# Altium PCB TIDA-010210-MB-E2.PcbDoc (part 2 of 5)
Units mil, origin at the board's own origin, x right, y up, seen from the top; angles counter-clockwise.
Board outline 11811.02 x 8661.42 mil, 4 copper layers (Top Layer, Gnd Layer, Pwr Layer, Bottom Layer), stack 94.4 mil thick; 473 components, 257 nets, 1291 pads, 289 vias.
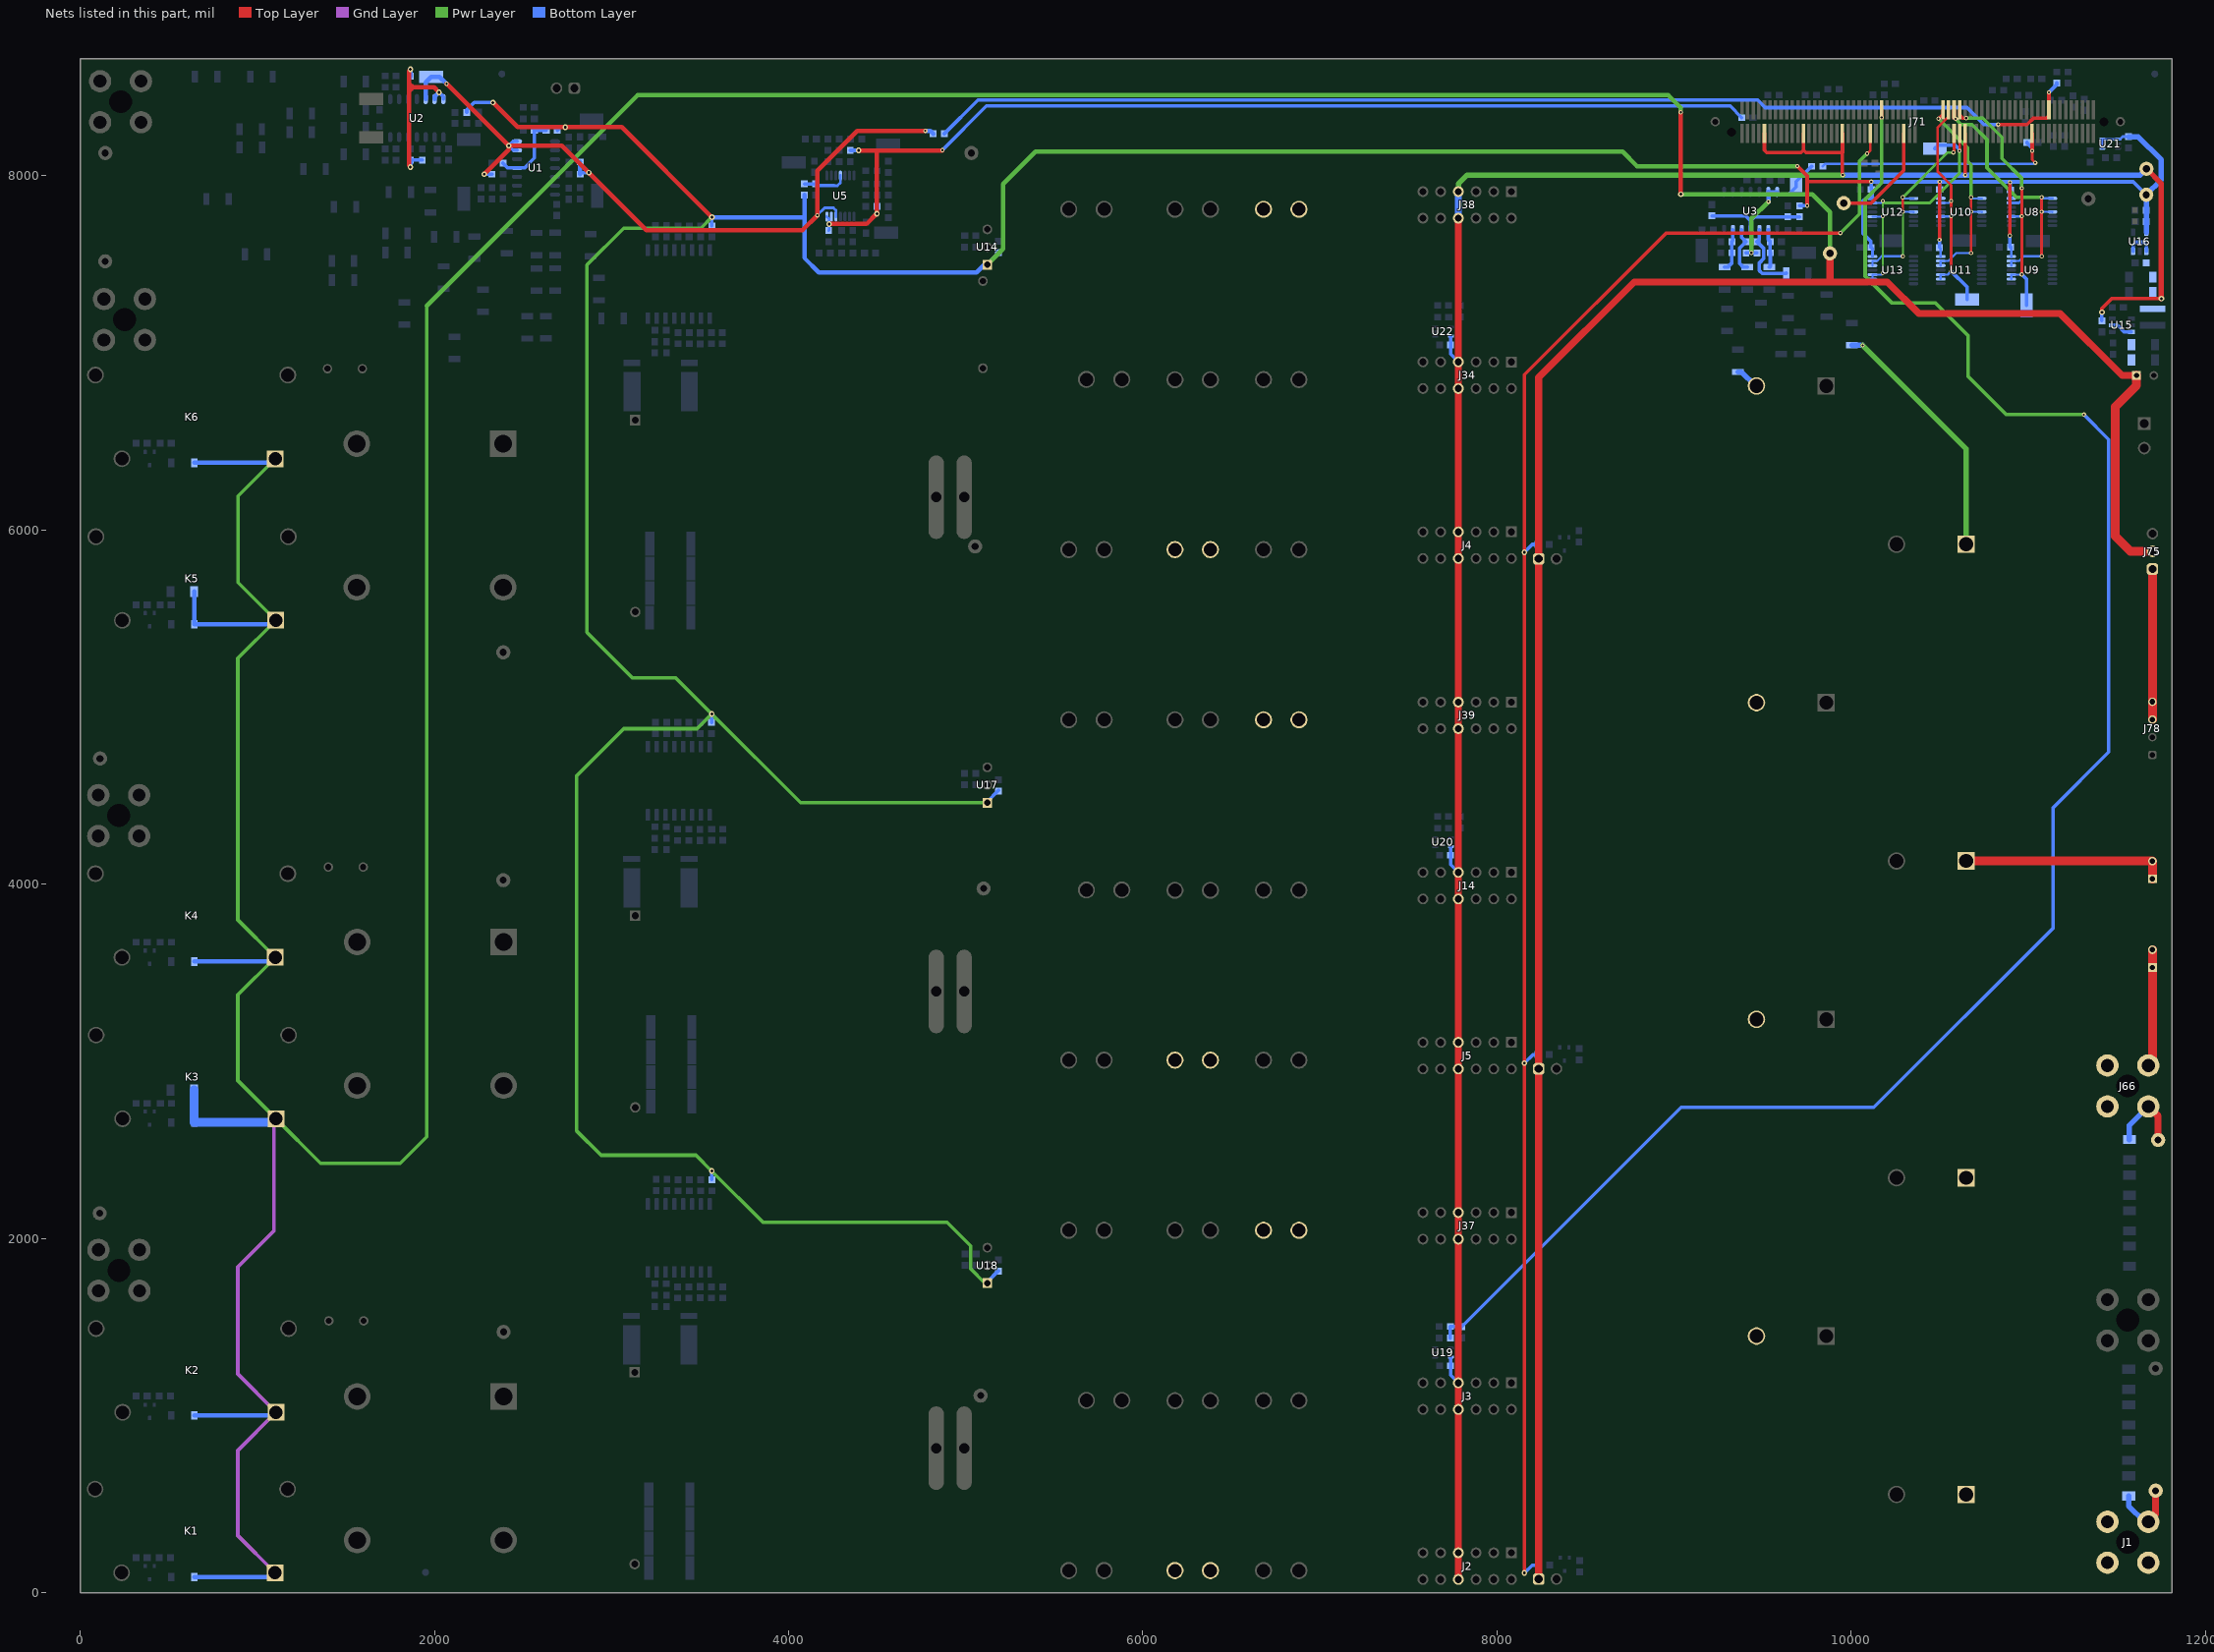
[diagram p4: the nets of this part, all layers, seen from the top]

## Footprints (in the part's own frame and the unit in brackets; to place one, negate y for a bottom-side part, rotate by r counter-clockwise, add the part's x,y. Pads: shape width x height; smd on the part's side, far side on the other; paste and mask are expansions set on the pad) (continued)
FP-7443783533220_PTH_34MM5_36MM-MFG [mm]
  rrect3% 3.8x3.8 hole 2.5 paste-1000 mask+0: 1(10.5,10.3)
  round 3.8 hole 2.5 paste-1000 mask+0: 2(-10.5,-10.3) 3(-10.5,10.3) 4(10.5,-10.3)
  silkscreen extent -18,-17.25 18.73,17.25, body extent -18.1,-17.35 18.1,17.35, height 0.25
IEC_Caution_Medium [mil]
  silkscreen extent -217,-182 217,193
IEC_HighVoltage_Medium [mil]
  silkscreen extent -217,-176 217,200
IEC_HotSurface_Medium [mil]
  silkscreen extent -217,-188 217,188
Keystone5000 [mil] "For Keystone 500x miniature loop terminals"
  round 80 hole 40: 1(0,0)
  silkscreen extent -52,-52 52,52, body extent -49,-49 49,49, height 182
Keystone5001 [mil] "For Keystone 500x miniature loop terminals"
  round 80 hole 40: 1(0,0)
  silkscreen extent -52,-52 52,52, body extent -49,-49 49,49, height 182
Keystone5002 [mil] "For Keystone 500x miniature loop terminals"
  round 80 hole 40: 1(0,0)
  silkscreen extent -52,-52 52,52, body extent -49,-49 49,49, height 182
Keystone5003 [mil] "For Keystone 500x miniature loop terminals"
  round 80 hole 40: 1(0,0)
  silkscreen extent -52,-52 52,52, body extent -49,-49 49,49, height 182
Keystone5004 [mil] "For Keystone 500x miniature loop terminals"
  round 80 hole 40: 1(0,0)
  silkscreen extent -52,-52 52,52, body extent -49,-49 49,49, height 182
Label_650x200 [mil] "Thermal Transfer Label"
  round 1 on Mech13: 0(0,0)
  silkscreen extent -325,-100 325,100, body extent -325,-100 325,100, height 1
LP0003A [mm] "TO, Flat Index; 3 In-Line, Formed Axial Leads; Body Dia. 4.8mm; Leads 0.56 x 0.41 mm (max)"
  rrect7% 1.4x1.4 hole 0.9: 1(0,2.54)
  round 1.4 hole 0.9: 2(0,0) 3(0,-2.54)
  silkscreen extent -1.35,-2.41 2.65,2.95, body extent -1.33,-2.83 2.35,2.83, height 9.01
Mill-max_310-13-102-41-001000 [mm] "Mill-Max"
  rect 1.25x1.25 hole 0.75: 1(-1.27,0)
  round 1.25 hole 0.75: 2(1.27,0)
  silkscreen extent -2.57,-1.3 2.58,1.73, body extent -2.54,-1.27 2.54,1.27, height 4.25
Mill-max_310-13-104-41-001000 [mm] "Receptacle, 2.54mm, 4x1, TH"
  rrect50% 1.2x1.2 hole 0.8 mask+0.05: 1(-3.81,0)
  round 1.2 hole 0.8 mask+0.05: 2(-1.27,0) 3(1.27,0) 4(3.81,0)
  body extent -5.08,-1.27 5.08,1.27, height 4.25
Mill-Max_0312-0-15-15-34-27-10-0 [mm] "Pin Receptacle, .032-.046\" .075\" Dia, Gold, TH"
  round 2.45 hole 1.905: 1(0,0)
  silkscreen extent -1.52,-1.52 1.52,1.52, body extent -1.15,-1.15 1.16,1.15, height 0.46
Molex_0448120024#1 [mm] "Receptacle, 2.54mm, 6x1, TH"
  round 1.55 hole 1.02: 1(-6.35,-1.905) 2(-3.81,-1.905) 2(-3.81,1.905) 3(-1.27,-1.905) 3(-1.27,1.905) 4(1.27,-1.905) 4(1.27,1.905) 5(3.81,-1.905) 5(3.81,1.905) 6(6.35,-1.905) 6(6.35,1.905)
  rect 1.55x1.55 hole 1.02: 1(-6.35,1.905)
  silkscreen extent -8.2,-4.09 8.08,3.4, body extent -7.92,-4.09 8.08,3.4, height 4.5
Molex_0448120024#2 [mm] "Receptacle, 2.54mm, 6x1, TH"
  rect 1.55x1.55 hole 1.02: 1(-6.35,-1.905)
  round 1.55 hole 1.02: 1(-6.35,1.905) 2(-3.81,-1.905) 2(-3.81,1.905) 3(-1.27,-1.905) 3(-1.27,1.905) 4(1.27,1.905) 4(1.27,-1.905) 5(3.81,-1.905) 5(3.81,1.905) 6(6.35,-1.905) 6(6.35,1.905)
  body extent -7.92,-3.4 8.08,4.09, height 4.5
Pb-Free_Overlay_Medium [mil]
  silkscreen extent -95,-95 95,95
PW0014A_N [mm] "TSOP, 14-Leads, Body 5x4.4mm, Pitch 0.65mm, IPC Medium Density"
  oval 1.4x0.45 smd: 1(-2.95,1.95) 2(-2.95,1.3) 3(-2.95,0.65) 4(-2.95,0) 5(-2.95,-0.65) 6(-2.95,-1.3) 7(-2.95,-1.95) 8(2.95,-1.95) 9(2.95,-1.3) 10(2.95,-0.65) 11(2.95,0) 12(2.95,0.65) 13(2.95,1.3) 14(2.95,1.95)
  silkscreen extent -3.4,-2.55 1.85,2.55, body extent -3.21,-2.5 3.21,2.5, height 1
RELAY_G4A-1A-PE [mm] "THD, 4-Leads, Body 30.5x16mm, Height 26.8mm"
  rect 2.4x2.4 hole 1.9: 1(-12,5.75)
  round 2.4 hole 1.9: 2(10,5.75) 3(13.8,-6.25) 4(-13.8,-6.25)
  silkscreen extent -16,-8 15.25,8, body extent -15.25,-8 15.25,8, height 26.8
SOD-123 [mm] "On Semi recommended land pattern"
  rect 0.915x1.22 smd: 1(-1.638,0) 2(1.637,0)
  silkscreen extent -2.74,-1.17 2.03,1.17, body extent -1.93,-0.9 1.93,0.9, height 1.35
SOT-323 [mm] "Diodes Inc recommended land pattern.  2016-02-24"
  rrect21% 0.6x0.47 smd: 1(-0.95,0.65) 2(-0.95,-0.65) 3(0.95,0)
  silkscreen extent -1.14,-1.22 0.77,1.22, body extent -1.13,-1.13 1.12,1.12, height 1.13
TDK_B751 [mm] "TH, 2-Leads, Dia 12.5mm, Pin Spacing 5mm"
  round 1.35 hole 0.85: 1(0,2.5) 2(0,-2.5)
  silkscreen extent -3.5,-6.25 3.5,6.25, body extent -3.48,-6.2 3.48,6.25, height 16.49
Testpoint_Keystone_Miniature [mil] "Miniature SMT test point"
  rect 135x70 smd: 1(0,0)
  silkscreen extent -78,-46 78,45, body extent -53,-20 53,20, height 61
TNPV1206 [mm] "VISHAY"
  rrect11% 0.9x1.7 smd: 1(-1.6,0) 2(1.6,0)
  silkscreen extent -2.4,-1.2 2.4,1.2, body extent -1.67,-0.87 1.67,0.87, height 0.65
VY1_1200x500_V [mm] "TH, 2-Leads, Body 12x5mm, Pin Spacing 12.5mm"
  round 1.4 hole 0.9: 1(-6.25,0) 2(6.25,0)
  silkscreen extent -3.5,-2.5 3.5,2.5, body extent -6.65,-2.5 6.65,2.5, height 15.99
WEEE_Minimum [mil] "WEEElie bin"
  silkscreen extent -95,-172 99,104
WL-SMCD-0603 [mm] "SMD, 2-Leads, Body 1.6x0.8mm"
  rrect13% 0.8x0.75 smd: 1(-0.8,0) 2(0.8,0)
  body extent -0.8,-0.4 0.8,0.4, height 0.4
WSL4026_310 [mm] "SMD, 4-Leads, Body 6.6x10.14mm"
  rect 2.44x5.6 smd: 1(-4.115,-0.9) 2(4.115,-0.9)
  rect 2.44x0.89 smd: 3(-4.115,3.235) 4(4.135,3.235)
  silkscreen extent -5.25,-3.5 5.1,3.5, body extent -5.15,-3.25 5.15,3.65, height 3.1
WURTH_61300211121 [mm] "Header, 2.54mm, 2x1, TH"
  rrect50% 1.65x1.65 hole 1.15: 1(-1.27,0)
  round 1.65 hole 1.15: 2(1.27,0)
  body extent -2.54,-1.27 2.54,1.27, height 8.54
WURTH_61300311121 [mm] "Header, 2.54mm, 3x1, TH"
  rrect50% 1.65x1.65 hole 1.15: 1(-2.54,0)
  round 1.65 hole 1.15: 2(0,0) 3(2.54,0)
  body extent -3.81,-1.27 3.81,1.27, height 8.54
Wurth_691214110002 [mm] "Receptacle, 3.5mm, 2x1, TH"
  rect 1.8x1.8 hole 1.3: 1(-1.75,0)
  round 1.8 hole 1.3: 2(1.75,0)
  silkscreen extent -3.8,-3.4 3.5,4, body extent -3.9,-3.4 3.5,4, height 8.5
Wurth_WP-THRBU [mm] "Power Element Bush, M3, TH"
  round 3.2 hole 1.85: 1(-2.935,-2.935) 1(-2.935,2.935) 1(2.935,-2.935) 1(2.935,2.935)
  round 3.1 on Top Paste: ""(-2.935,-2.935) ""(-2.935,2.935) ""(2.935,-2.935) ""(2.935,2.935)
  round 3 hole 3.3 unplated mask+0.102: ""(0,0)
  silkscreen extent -3.5,-3.5 3.5,3.5, body extent -3.5,-3.5 3.5,3.5, height 3
XAL4030 [mil] "Coilcraft XAL4030 7/18/12"
  rect 38x146 smd: 1(-46.5,0) 2(46.5,0)
  silkscreen extent -84,-84 84,84, body extent -84,-84 84,84, height 122

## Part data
C1 C2 C3 C4 C5 C6 C7 C8: library part LGN2X121MELB45, "CAP, AL, 150 uF, 550 V, +/- 20%, TH", Cap_Case=22x45mm, Manufacturer=Kemet, Tolerance_%=20, Value2=550V, ValueDisplayed=150µF
C9 C10 C11: library part CMP-0012442-3, "CAP, Film, 4.7 uF, 630 V, +/- 10%, 0.015 ohm, TH", Manufacturer=TDK, Tolerance_%=10%, Value1="0.015 ohm", Value2=630V, ValueDisplayed=4.7uF
C12 C87 C88 C105: library part CMP-0008772-2, "CAP, CERM, 10 uF, 35 V, +/- 10%, X7R, AEC-Q200 Grade 1, 1206_190", Cap_Case=1206_190, Manufacturer=TDK, Supplier Part Number 1=445-174428-1-ND, TempCo=X7R, Tolerance_%=10%, Value1="0.002229 ohm", Value2=35V, ValueDisplayed=10uF
C13: library part CMP-0064961-1, "CAP, CERM, 2200 pF, X1 760 VAC/Y1 500 VAC, +/- 10%, Y5U, D12xT5mm", Cap_Case=12x5mm, Manufacturer=Vishay-Bccomponents, TempCo=Y5U, Tolerance_%=10%, Value1=Unknown, Value2=V, ValueDisplayed=2200pF
C14 C15 C16 C20 C21 C22 C26 C27: library part CMP-0006790-4, "CAP, CERM, 470 pF, 50 V, +/- 5%, C0G/NP0, 0603", Cap_Case=0603, Manufacturer=AVX, Supplier Part Number 1=478-1183-1-ND, TempCo=C0G/NP0, Tolerance_%=5%, Value1="0.063 ohm", Value2=50V, ValueDisplayed=470pF
C17 C18 C19 C23 C24 C25 C28 C29 C31 C36 C50 C63 C74: "CAP, CERM, 0.01uF, 50V, +/-10%, X7R, 0603", Cap_Case=0603, Manufacturer=Kemet, Supplier Part Number 1=399-5346-1-ND, TempCo=X7R, Tolerance_%=10, Value1=Unknown, Value2=50V, ValueDisplayed=0.01µF
C30 C32 C33 C34 C37 C41 C45 C46 C54 C58 C59 C67 C71 C72 C73 C77 C78 C79 C80 C81 C82 C83 C84 C85 C93 C94 C96 C97 C98 C100 C101 C102 C104: library part CMP-0006979-5, "CAP, CERM, 0.1 uF, 25 V, +/- 10%, X7R, 0603", Cap_Case=0603, Manufacturer=Kemet, Supplier Part Number 1=399-5345-1-ND, TempCo=X7R, Tolerance_%=10%, Value1=Unknown, Value2=25V, ValueDisplayed=0.1uF
C35 C49 C62: library part CMP-0007210-4, "CAP, CERM, 3300 pF, 50 V, +/- 5%, C0G/NP0, 0603", Cap_Case=0603, Manufacturer=MuRata, Supplier Part Number 1=GRM1885C1H332JA01D-ND, TempCo=C0G/NP0, Tolerance_%=5%, Value1=Unknown, Value2=50V, ValueDisplayed=3300pF
C38 C51 C64: library part CMP-0007197-4, "CAP, CERM, 220 pF, 50 V, +/- 5%, C0G/NP0, 0603", Cap_Case=0603, Manufacturer=MuRata, Supplier Part Number 1=490-1435-1-ND, TempCo=C0G/NP0, Tolerance_%=5%, Value1=Unknown, Value2=50V, ValueDisplayed=220pF
C39 C42 C52 C55 C65 C68 C95 C99 C103: library part CMP-0006784-4, "CAP, CERM, 330 pF, 50 V, +/- 5%, C0G/NP0, 0603", Cap_Case=0603, Manufacturer=AVX, Supplier Part Number 1=478-1181-1-ND, TempCo=C0G/NP0, Tolerance_%=5%, Value1="0.071 ohm", Value2=50V, ValueDisplayed=330pF
C40 C44 C53 C57 C66 C70: library part CMP-0079720-1, "CAP, CERM, 1 µF, 25 V,+/- 10%, X7R, 0603", Cap_Case=0603, Manufacturer=MuRata, Supplier Part Number 1=490-10888-1-ND, TempCo=X7R, Tolerance_%=10%, Value2=25V, ValueDisplayed=1µF
C43 C47 C48 C56 C60 C61 C69 C75 C76: library part CMP-0007431-4, "CAP, CERM, 1000 pF, 50 V, +/- 5%, X7R, 0603", Cap_Case=0603, Manufacturer=MuRata, Supplier Part Number 1=490-9733-1-ND, TempCo=X7R, Tolerance_%=5%, Value1=Unknown, Value2=50V, ValueDisplayed=1000pF
C86: library part CMP-0010333-1, "CAP, AL, 100 uF, 25 V, +/- 20%, TH", Cap_Case="Radial 6.3x11.2", Manufacturer=Panasonic, Supplier Part Number 1=P13476-ND, Tolerance_%=20%, Value1=Unknown, Value2=25V, ValueDisplayed=100uF
C89 C90: library part CMP-0008959-2, "CAP, CERM, 22 uF, 10 V, +/- 10%, X7R, 1206", Cap_Case=1206, Manufacturer=MuRata, Supplier Part Number 1=490-5309-1-ND, TempCo=X7R, Tolerance_%=10%, Value1=Unknown, Value2=10V, ValueDisplayed=22uF
C91 C92: library part CMP-0079605-1, "CAP, CERM, 2.2 µF, 16 V,+/- 10%, X7R, 0603", Cap_Case=0603, Manufacturer="Yageo America", Supplier Part Number 1=311-3490-1-ND, TempCo=X7R, Tolerance_%=10%, Value2=16V, ValueDisplayed=2.2µF
D1 D2 D3 D4 D5 D6: library part CMP-0750148-1, "Diode, Switching, 100 V, 0.3 A, AEC-Q101, SOD-123", Manufacturer="Diodes Inc.", Value1=0.3A, Value2=1.25V
D7 D8: library part CMP-0081648-2, "LED, Green, SMD", Color=Green, Manufacturer="Wurth Elektronik", Power_TotalModule=48mW, Value1=0.048W, Value2=2V
FID1 FID2 FID3: library part CMP-0077181-1, "Fiducial mark.  There is nothing to buy or mount.", Manufacturer=N/A
J1 J31 J66 J67 J68 J69 J70: library part CMP-0078526-1, "Power Element Bush, M3, TH", Current_A=50A, Manufacturer="Wurth Elektronik", Supplier Part Number 1=732-10882-1-ND
J2 J3 J4 J5 J14 J34 J37 J38 J39: "Receptacle, 2.54mm, 6x1, Gold, TH", Manufacturer=Molex, Supplier Part Number 1=WM18605-ND
J6 J7 J8 J9 J10 J11 J12 J13 J15 J16 J17 J18 J19 J20 J21 J22 J23 J24 J25 J26 J27 J28 J29 J30 J32 J33 J35 J36 J40 J41 J42 J43 J44 J45 J46 J47 J48 J49 J50 J51 J52 J53 J54 J55 J56 J57 J58 J59 J60 J61 J62 J63 J64 J65: library part 0312-0-15-15-34-27-10-0, "Pin Receptacle, .032-.046\" .075\" Dia, Gold, TH", Manufacturer=Mill-Max, Supplier Part Number 1=0312-015153427100-ND
J71: library part CMP-0003814-2, "C2000 controlCARD-120HSEC connector, SMT", Manufacturer=Samtec
J72 J79 J80 J81: library part CMP-0054794-2, "Header, 2.54 mm, 2x1, Gold, TH", Color=Black, Manufacturer="Wurth Elektronik", Supplier Part Number 1=732-5315-ND
J74: library part CMP-0054825-2, "Terminal Block, 3.5mm, 2x1, Tin, TH", Color=Green, Current_A=10A, Manufacturer="Wurth Elektronik", Supplier Part Number 1=732-2747-ND, Voltage_V=300V
J75: library part CMP-0054796-2, "Header, 2.54 mm, 3x1, Gold, TH", Color=Black, Manufacturer="Wurth Elektronik", Supplier Part Number 1=732-5316-ND
J76 J77: library part CMP-0055073-1, "Socket Strip, 100mil, 2x1, Gold, TH", Manufacturer=Mill-Max, Supplier Part Number 1=ED7402-ND
J78: library part CMP-0084081-1, "Receptacle, 2.54mm, 4x1, TH", Color=Black, Manufacturer=Mill-Max
K1 K2 K3 K4 K5 K6: library part CMP-0002594-2, "Relay, SPST-NO (1 Form A), 20 A, 12 V, TH", Coil Current_A=75mA, Coil Power_W=900mW, Coil Resistance_ohm=160, Coil Voltage_VDC=12V, Contact Rating_A=20A, Manufacturer="Omron Electronic Components", Supplier Part Number 1=Z954-ND, Turn Off Voltage (Min)_VDC=1.2V, Turn On Voltage (Max)_VDC=8.4V
L1 L3 L5: library part CMP-0087414-1, "IND 22uH TOL 20%", Manufacturer="Wurth Electronics"
L2 L4 L6: library part G154017LF, "Inductor, 480uH, 15 A, 0.060 ohm, TH", Manufacturer="Wurth Elektronik", Value1="0.060 ohm", Value2=15A, ValueDisplayed=480uH
L7 L8 L9 L10 L11 L12 L13: library part CMP-0003155-2, "Ferrite Bead, 26 ohm @ 100 MHz, 6.5 A, 0603", Manufacturer="Wurth Elektronik", Supplier Part Number 1=732-6117-1-ND, Value1="0.005 ohm", Value2=6.5A, ValueDisplayed="26 ohm"
L14: library part CMP-0060989-1, "Inductor, Shielded, Composite, 3.3 uH, 5.5 A, 0.026 ohm, SMD", Manufacturer=Coilcraft, Supplier Part Number 1=994-XAL4030-332MEB, Value1="0.026 ohm", Value2=5.5A, ValueDisplayed=3.3uH
LBL1: library part CMP-0003625-1, "Thermal Transfer Printable Labels, 0.650\" W x 0.200\" H - 10,000 per roll", Manufacturer=Brady, Supplier Part Number 1=97C5133
Logo1: library part CMP-0074769-1
Logo2: library part CMP-0074839-1
Logo3: library part CMP-0074847-1, "FCC_disclaimer"
Logo4: library part CMP-0074836-1, "IEC 61010-1 Caution Warning"
Logo5: library part CMP-0074840-1, "ESD Susceptible Symbol"
LOGO6 LOGO7 LOGO8 LOGO9 LOGO13: library part CMP-0074835-1, "IEC 61010-1 High Voltage Warning"
LOGO10 LOGO11 LOGO12 LOGO16 LOGO17: library part CMP-0074837-1, "IEC 61010-1 Hot Surface Warning"
Logo15: library part CMP-0074844-1
Q1 Q2 Q3 Q4 Q5 Q6 Q7 Q8 Q9: library part CMP-0000790-2, "MOSFET, N-CH, 60 V, 0.32 A, AEC-Q101, SOT-323", Alternate Manufacturer=None, Manufacturer=Nexperia, Supplier Part Number 1=568-10309-1-ND, Value2="0.72 nC"
R1 R2 R4 R5 R7 R8 R10 R11: library part CMP-0017836-2, "RES, 100 k, 1%, 0.25 W, 1206", Manufacturer="Yageo America", Power_W=250mW, Supplier Part Number 1=311-100KFRCT-ND, TempCo="100 ppm/C", Tolerance_%=1%, Value2=0.25W, Value_Code=100k
R3 R6 R9: library part CMP-0015295-2, "RES, 0.002, 1%, 3 W, AEC-Q200 Grade 0, 4026", Manufacturer=Vishay-Dale, Power_W=3W, Supplier Part Number 1=WSLR-.002CT-ND, TempCo="75 ppm/C", Tolerance_%=1%, Value_Code=2L000, ValueDisplayed=0.002
R12 R13 R14 R15 R16 R17 R18 R19 R20 R162 R163 R164: library part CMP-0015862-2, "RES, 2.2, 5%, 3 W, 2512", Manufacturer="TE Connectivity", Power_W=3W, Supplier Part Number 1=A121213CT-ND, TempCo=ppm/C, Tolerance_%=5%, Value_Code=2R20, ValueDisplayed=2.2
R21 R22 R23 R24 R25 R26 R149 R153 R158: library part CMP-0025882-3, "RES, 100, 5%, 0.25 W, AEC-Q200 Grade 0, 0603", Manufacturer=Rohm, Power_W=250mW, Supplier Part Number 1=RHM100DCT-ND, TempCo="200 ppm/C", Tolerance_%=5%, Value2=0.25W, Value_Code=100R, ValueDisplayed=100
R27 R28 R29 R30 R31 R32 R145 R151 R155 R160: library part CMP-0022684-3, "RES, 10.0 k, 1%, 0.1 W, 0603", Manufacturer=Panasonic, Power_W=100mW, Supplier Part Number 1=P10.0KHCT-ND, TempCo="100 ppm/C", Tolerance_%=1%, Value2=0.1W, Value_Code=10k0, ValueDisplayed=10.0k
R33 R34 R57 R58 R60 R61 R84 R85 R87 R88 R103 R104: library part CMP-0023423-3, "RES, 12.0 k, 0.1%, 0.1 W, 0603", Manufacturer="Susumu Co Ltd", Power_W=100mW, Supplier Part Number 1=RG16P12.0KBCT-ND, TempCo="25 ppm/C", Tolerance_%=0.1%, Value2=0.1W, Value_Code=12k0, ValueDisplayed=12.0k
R35 R59 R62 R86: library part CMP-0023649-3, "RES, 10.5 k, 0.1%, 0.1 W, 0603", Manufacturer="Yageo America", Power_W=100mW, TempCo="25 ppm/C", Tolerance_%=0.1%, Value2=0.1W, Value_Code=10k5, ValueDisplayed=10.5k
R36 R37 R38 R39 R40 R41 R42 R43 R44 R48 R49 R50 R51 R52 R53 R54 R55 R56 R63 R64 R65 R66 R67 R68 R69 R70 R71 R75 R76 R77 R78 R79 R80 R81 R82 R83 R89 R90 R91 R92 R93 R94 R97 R98 R99 R100 R101 R102: library part CMP-0018805-2, "RES, 1.00 M, 0.1%, 1 W, 1206", Manufacturer="Vishay Draloric", Power_W=1W, Supplier Part Number 1=541-2320-1-ND, TempCo="25 ppm/C", Tolerance_%=0.1%, Value_Code=1M00, ValueDisplayed=1.00M
R45 R46 R47 R72 R73 R74 R95 R96 R108 R140: library part CMP-0022553-4, "RES, 68.1, 1%, 0.1 W, AEC-Q200 Grade 0, 0603", Manufacturer=Vishay-Dale, Power_W=100mW, Supplier Part Number 1=541-68.1HCT-ND, TempCo="100 ppm/C", Tolerance_%=1%, Value2=0.1W, Value_Code=68R1, ValueDisplayed=68.1
R105 R106 R109 R110: library part CMP-0081973-1, "RES, 0, 0%, 0.25 W, AEC-Q200 Grade 0, 0603", Manufacturer=Vishay-Dale, Power_W=250mW, Supplier Part Number 1=541-2779-1-ND, Tolerance_%=0%, Value2=0.25W, Value_Code=0
R107 R111 R138 R141: library part CMP-0023404-3, "RES, 10.0 k, 0.1%, 0.1 W, 0603", Manufacturer="Susumu Co Ltd", Power_W=100mW, Supplier Part Number 1=RG16P10.0KBCT-ND, TempCo="25 ppm/C", Tolerance_%=0.1%, Value2=0.1W, Value_Code=10k0, ValueDisplayed=10.0k
R112 R120 R121 R129 R130 R139: "RES, 10.0 k, 0.1%, 0.0375 W, 0603", Manufacturer="Vishay Sfernice", Power_W=0.0375, Supplier Part Number 1=PHTB-10KCT-ND, TempCo="15 ppm/C", Tolerance_%=0.1, Value1=0.1%, Value2=0.0375W, Value_Code=10k0, ValueDisplayed=10.0k
R113 R117 R122 R126 R131 R135: library part CMP-0023143-5, "RES, 49.9, 1%, 0.1 W, 0603", Manufacturer=Yageo, Power_W=100mW, Supplier Part Number 1=311-49.9HRCT-ND, TempCo="100 ppm/C", Tolerance_%=1%, Value2=0.1W, Value_Code=49R9, ValueDisplayed=49.9
R114 R118 R123 R127 R132 R136: library part CMP-0023780-3, "RES, 15.0 k, 0.1%, 0.1 W, 0603", Manufacturer="Yageo America", Power_W=100mW, TempCo="25 ppm/C", Tolerance_%=0.1%, Value2=0.1W, Value_Code=15k0, ValueDisplayed=15.0k
R115 R119 R124 R128 R133 R137: library part CMP-0022003-4, "RES, 10.0, 1%, 0.1 W, AEC-Q200 Grade 0, 0603", Manufacturer=Vishay-Dale, Power_W=100mW, Supplier Part Number 1=541-10.0HCT-ND, TempCo="100 ppm/C", Tolerance_%=1%, Value2=0.1W, Value_Code=10R0, ValueDisplayed=10.0
R116 R125 R134: library part CMP-0082532-1, "RES, 499, 1%, 0.1 W, 0603", Manufacturer=Vishay-Dale, Power_W=100mW, Supplier Part Number 1=541-3986-1-ND, TempCo="100 ppm/C", Tolerance_%=1%, Value2=0.1W, Value_Code=499R, ValueDisplayed=499
R142 R146 R148 R156: library part CMP-0022985-5, "RES, 2.26 k, 1%, 0.1 W, 0603", Manufacturer=Yageo, Power_W=100mW, Supplier Part Number 1=311-2.26KHRCT-ND, TempCo="100 ppm/C", Tolerance_%=1%, Value2=0.1W, Value_Code=2k26, ValueDisplayed=2.26k
R143 R161: library part CMP-0023288-5, "RES, 820, 1%, 0.1 W, 0603", Manufacturer=Yageo, Power_W=100mW, Supplier Part Number 1=311-820HRCT-ND, TempCo="100 ppm/C", Tolerance_%=1%, Value2=0.1W, Value_Code=820R, ValueDisplayed=820
R144: library part CMP-0023186-5, "RES, 56.2 k, 1%, 0.1 W, 0603", Manufacturer=Yageo, Power_W=100mW, Supplier Part Number 1=311-56.2KHRCT-ND, TempCo="100 ppm/C", Tolerance_%=1%, Value2=0.1W, Value_Code=56k2, ValueDisplayed=56.2k
R147 R152 R157: library part CMP-0022886-5, "RES, 1.69 k, 1%, 0.1 W, 0603", Manufacturer=Yageo, Power_W=100mW, Supplier Part Number 1=311-1.69KHRCT-ND, TempCo="100 ppm/C", Tolerance_%=1%, Value2=0.1W, Value_Code=1k69, ValueDisplayed=1.69k
R150 R154 R159: library part CMP-0023081-5, "RES, 3.30 k, 1%, 0.1 W, 0603", Manufacturer=Yageo, Power_W=100mW, Supplier Part Number 1=311-3.30KHRCT-ND, TempCo="100 ppm/C", Tolerance_%=1%, Value2=0.1W, Value_Code=3k30, ValueDisplayed=3.30k
RT1 RT2 RT3: "Thermistor NTC, 50 ohm, 25%, D12.5xH16.5mm", Manufacturer=TDK, Supplier Part Number 1=495-3880-ND, Tolerance_%=25
TP1 TP14 TP35 TP36 TP38: library part CMP-0055137-1, "Test Point, Miniature, Red, TH", Color=Red, Manufacturer=Keystone, Supplier Part Number 1=36-5000-ND
TP2 TP4 TP7 TP10 TP11 TP12: library part CMP-0055140-1, "Test Point, Miniature, Orange, TH", Color=Orange, Manufacturer=Keystone, Supplier Part Number 1=36-5003-ND
TP3 TP6 TP8: library part CMP-0055139-1, "Test Point, Miniature, White, TH", Color=White, Manufacturer=Keystone, Supplier Part Number 1=36-5002-ND
TP5 TP13 TP15 TP37: library part CMP-0055138-1, "Test Point, Miniature, Black, TH", Color=Black, Manufacturer=Keystone, Supplier Part Number 1=36-5001-ND
TP9: library part CMP-0055141-1, "Test Point, Miniature, Yellow, TH", Color=Yellow, Manufacturer=Keystone, Supplier Part Number 1=36-5004-ND
TP16 TP17 TP18 TP19 TP20 TP21 TP22 TP23 TP24 TP25 TP26 TP27 TP28 TP29 TP30 TP31 TP32 TP33 TP34: "Test Point, Miniature, SMT", Manufacturer=Keystone, Supplier Part Number 1=36-5015TR-ND
U1 U2 U3: library part CMP-0860066-1, "4-Channel, 1MHz, RRIO, 1.8V to 5.5V Operational Amplifier for Cost-Optimized Systems, D0014A (SOIC-14)", Alternate Manufacturer="Texas Instruments", Operating Temperature Range="-40 to 125 C", Rating=Catalog
U4 U6 U7: library part CMP-0750211-1, "AMC3301 Precision, ±250-mV Input, Reinforced Isolated Amplifier with Integraded DC/DC Converter, DWE0016A (SO-MOD-16)", Alternate Manufacturer="Texas Instruments", Alternate PartNumber=AMC3301DWE, PartNumber=AMC3302DWER
U5: library part CMP-0041164-1, "Precision, Low Noise, Low Quiescent Current Operational Amplifier, 2 to 5.5 V, -40 to 125 degC, 14-pin SOP (PW14), Green (RoHS & no Sb/Br)", Manufacturer="Texas Instruments", Total Supply Voltage(Max)(+5V is 5, +/-5V is 10)=5.5, Total Supply Voltage(Min)(+5V is 5, +/-5V is 10)=2
U8 U10 U12: library part CMP-0054477-1, "Quadruple 2-Input Positive-AND Gate, PW0014A, LARGE T&R", F @ Nom Voltage(Max)(Mhz)=70, Generic Part Number=SN74LVC08A, ICC @ Nom Voltage(Max)(mA)=0.01, Manufacturer="Texas Instruments", Operating Temperature Range(C)="-40 to 125", Rating=Catalog, tpd @ Nom Voltage(Max)(ns)=9.8,6.9,4.8,4.1, Voltage(Nom)(V)=1.8,2.5,2.7,3.3
U9 U11 U13: library part CMP-0050882-1, "Quadruple 2-Input Positive-OR Gate, PW0014A, LARGE T&R", F @ Nom Voltage(Max)(Mhz)=70, Generic Part Number=SN74LVC32A, ICC @ Nom Voltage(Max)(mA)=0.04, Manufacturer="Texas Instruments", Operating Temperature Range(C)="-40 to 105,-40 to 125", Rating=Catalog, tpd @ Nom Voltage(Max)(ns)=8.7,5.4,4.4,3.8, Voltage(Nom)(V)=1.8,2.5,2.7,3.3
U14 U17 U18: library part CMP-0076507-3, "2.7V-Capable, 10 uA Analog Output Temperature Sensor in SC70 and TO-92, LP0003A (TO-92-3)", Alternate Manufacturer="Texas Instruments", Alternate PartNumber=LMT87LP, Operating Temperature Range="-50 to 150 C", Rating=Catalog
U15: library part CMP-0067070-2, "17 V Input, 3A Synchronous Step-Down Regulator in SOT-23 with Advanced Eco-mode(TM), DDC0006A (SOT-23-T-6)", Alternate Manufacturer="Texas Instruments", Alternate PartNumber=TPS563200DDCT
U16: library part CMP-0066020-1, "250-mA Ultra-Low-Noise, Low-IQ LDO, DBV0005A (SOT-23-5)", Alternate Manufacturer="Texas Instruments"
U19 U20 U22: library part CMP-0051559-1, "Single 2-Input Positive-AND Gate, DCK0005A, SMALL T&R", F @ Nom Voltage(Max)(Mhz)=150, Generic Part Number=SN74LVC1G08, ICC @ Nom Voltage(Max)(mA)=0.01, Manufacturer="Texas Instruments", Operating Temperature Range(C)="-40 to 125,-40 to 85", Rating=Catalog, tpd @ Nom Voltage(Max)(ns)=4.5,6,4,5, Voltage(Nom)(V)=1.8,2.5,3.3,5
U21: library part CMP-0066236-2, "Automotive Grade, 2.7V-Capable, 10 uA Analog Output Temperature Sensor, DCK0005A (SOT-SC70-5)", Alternate Manufacturer="Texas Instruments", Alternate PartNumber=LMT87QDCKTQ1
ZZ1: library part CMP-0003616-3
ZZ2: library part CMP-0077236-1
ZZ3: library part CMP-0077237-1
ZZ4: library part CMP-0077238-1

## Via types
v1: diameter 24, hole 12, Top Layer to Bottom Layer, tented both sides, 169 vias
v2: diameter 32, hole 16, Top Layer to Bottom Layer, tented both sides, 102 vias
v3: diameter 50, hole 28, Top Layer to Bottom Layer, tented both sides, 18 vias

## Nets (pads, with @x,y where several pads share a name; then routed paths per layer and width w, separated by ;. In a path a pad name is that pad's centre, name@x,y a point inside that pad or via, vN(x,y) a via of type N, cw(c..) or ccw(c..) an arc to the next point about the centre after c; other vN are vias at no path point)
1.65V_1: R57.1 R84.1 R103.1 R140.1 TP24.1 U1.6 U1.7 U2.12 U5.12 | length 4371.8
  Top Layer w25: v1(2069,8519) 2070,8519 v2(2420,8169) ; v2(2281.75,8008.53) 2420,8146.78 v2(2420,8169) ; v1(4772,8253) 4387,8253 4162,8028 v1(4162,7776.08) 4162,7776 4078,7692 3197,7692 v2(2872,8017) 2720,8169 v2(2420,8169)
  Bottom Layer w15: v1(4162,7776.08) 4203.92,7818 4253.18,7818 4266.91,7804.27 U5.12@4266.91,7768.77
  Bottom Layer w20: v2(2281.75,8008.53) R57.1@2324.34,8008.53 R57.1@2324.86,8008 ; U1.6@2466.55,8143.53 2445.47,8143.53 v2(2420,8169) 2444.53,8193.53 U1.7@2466.55,8193.53 ; R84.1@2832.92,8017 v2(2872,8017) v2@2877.94,8017
  Bottom Layer w25: U2.12@1950.98,8432.25 1950.98,8527.27 TP24.1@1982,8558.3 2029.7,8558.3 v1(2069,8519) ; R103.1@2823.21,8078.05 2823.21,8008.57 R84.1@2823.33,8008.46 ; v1(4772,8253) 4800.5,8253 R140.1@4816.5,8237
1.65V_1S: C74.1 J71.17 R140.2 | length 6595.6
  Top Layer w20: v1(10829,8289) 10992.23,8289 11026.89,8323.66 11100.78,8323.66 11115.4,8338.28 J71.17@11115.4,8371.93 11115.4,8469.58 v1(11114.99,8470)
  Bottom Layer w20: R140.2@4879.5,8237 5069.5,8427 9471,8427 9513.76,8384.24 10653.76,8384.24 10749,8289 v1(10829,8289) ; v1(11114.99,8470) 11159.68,8514.69 C74.1@11159.68,8523
1.65V_2: R59.1 R86.1 R108.1 TP25.1 U3.13 U3.14 | length 781.9
  Pwr Layer w25: v1(9436.08,7564.13) 9436.08,7757.92 v1(9532,7853.84)
  Bottom Layer w20: R86.1@9405.17,7564.13 v1(9436.08,7564.13) R59.1@9467,7564.13 ; U3.13@9531.14,7908.56 U3.14@9581.14,7908.56 9598.07,7891.63 9643.7,7891.63 9688.64,7936.57 TP25.1@9688.64,7948.98 9688.64,7966.13 R108.1@9775.5,8053
  Bottom Layer w25: U3.13@9531.14,7908.56 9532,7907.7 v1(9532,7853.84)
1.65V_2S: C31.1 J71.24 R108.2 | length 1440
  Top Layer w15: v1(11021,8139.99) 11021,8090 11038,8073 v1(11038.3,8073)
  Top Layer w20: J71.24@11020.92,8238.07 11020.92,8140.07 v1(11021,8139.99)
  Bottom Layer w15: R108.2@9838.5,8053 9851.5,8066 11031.3,8066 v1(11038.3,8073)
  Bottom Layer w20: C31.1@10991,8187 10991,8186.33 11021,8156.33 v1(11021,8139.99)
1.65V_A: R58.1 R85.1 R104.1 U2.13 U2.14 | length 1026.5
  Top Layer w25: 1856,8475.24 1879.38,8498.62 ; v2(1865,8048.94) 1856,8057.94 1856,8522 ; v2(1865,8601) 1856,8592 1856,8522 ; v2(2026,8470.38) 1997.76,8498.62 1879.38,8498.62 ; 1856,8522 1879.38,8498.62
  Bottom Layer w20: R85.1@1865,8088.44 R58.1@1931.53,8088.44 ; v2(2026,8470.38) 2050.98,8445.4 U2.14@2050.98,8432.25
  Bottom Layer w25: v2(1865,8048.94) R85.1@1865,8088.44 ; R104.1@1865,8561.5 v2(1865,8601) ; U2.13@2000.98,8432.25 2000.98,8445.35 v2(2026,8470.38)
1.65V_C: R110.1 R120.1 R129.1 R139.1 U5.13 U5.14 | length 5940.6
  Top Layer w25: v2(4229,7727.07) 4439.94,7727.07 v2(4498.5,7785.63) 4498.5,8142.13 ; v2(4395.5,8142.63) 4396,8142.13 4498.5,8142.13 ; v1(4868,8144) 4866.63,8142.63 4499,8142.63 4498.5,8142.13
  Bottom Layer w15: U5.14@4215.73,7768.77 4229,7755.5 v2(4229,7727.07) 4229,7693.63 R139.1@4226,7690.63
  Bottom Layer w20: R120.1@4348.47,8142.41 4348.7,8142.63 v2(4395.5,8142.63) ; v2(4498.5,7785.63) 4498.5,7826.44 R129.1@4498.97,7826.91 ; v1(4868,8144) 5117.33,8393.33 9315.68,8393.33 R110.1@9381.01,8328
3.3V: C77.2 C78.2 C79.2 C80.2 C81.2 C82.2 C84.2 C92.1 C93.2 C97.2 C102.2 L7.1 L8.1 L9.1 L10.1 L11.2 L12.2 L13.2 R143.1 TP36.1 U8.14 U9.14 U10.14 U11.14 U12.14 U13.14 U14.1 U16.5 U17.1 U18.1 U21.1 U21.4 U21.5 | length 25068.5
  Top Layer w20: v1(9695,8054) 9750.5,7998.5 9750.5,7966 ; v1(9750.5,7830.5) 9750.5,7966 ; v1(10113,7966) 9750.5,7966 ; v1(10497.64,7637.56) 10498.96,7638.88 v1(10498.96,7965.54) ; v1(10894.89,7661.66) 10895.89,7662.66 v1(10895.89,7962.54)
  Top Layer w25: v2(2331,8413) 2470,8274 v2(2739,8274) 3057.99,8274 v2(3566.5,7765.5)
  Pwr Layer w20: v2(3566.5,7765.5) 3505,7704 3069,7704 2861,7496 2861,5422 3119,5164 3363.92,5164 v2(3566.43,4961.5) ; U18.1@5121.95,1748 5108,1748 5027,1829 5027,1958 4894,2091 3855.93,2091 v2(3566.43,2380.5) 3476.93,2470 2941,2470 2802,2609 2802,4610 3070,4878 3482.93,4878 v2(3566.43,4961.5) ; U17.1@5121.95,4460 4067.92,4460 v2(3566.43,4961.5)
  Pwr Layer w25: U14.1@5122,7497 5211.05,7586.05 5211,7586.1 5211,7953 5394,8136 8708,8136 8790,8054 v1(9695,8054)
  Bottom Layer w15: C78.2@10113.68,7594.44 10119.04,7589.08 U13.14@10119.04,7543.48 ; U12.14@10119.04,7872.7 C81.2@10119.04,7917.16 ; C77.2@10499.55,7922.18 10504.18,7917.55 U10.14@10504.18,7871.95 ; U11.14@10504.18,7543.87 C80.2@10504.18,7589.47 ; C79.2@10898.85,7596.18 10903.21,7591.81 U9.14@10903.21,7543.87 ; U21.4@11417.15,8154.75 U21.5@11417.15,8205.93 ; U21.5@11417.31,8206.09 U21.1@11505.73,8206.09 ; U21.1@11505.73,8205.93 11517.84,8205.93 11532.15,8220.25 C102.2@11564.73,8220.25
  Bottom Layer w20: L8.1@2182.98,8357.47 2182.98,8370.98 2225,8413 v2(2331,8413) ; L7.1@2693.95,8255.85 2712.1,8274 v2(2739,8274) ; L11.2@3566.43,2331.78 v2(3566.43,2380.5) ; L12.2@3566.43,4912.78 v2(3566.43,4961.5) ; L13.2@3566.5,7716.78 v2(3566.5,7765.5) ; U18.1@5121.95,1748 5121.95,1754.51 C97.2@5185,1817.56 ; U17.1@5121.95,4460 5121.95,4466.51 C93.2@5185,4529.56 ; U14.1@5122,7497 5122,7503.51 C84.2@5185.05,7566.56 ; L9.1@9707,7830.5 v1(9750.5,7830.5) ; C78.2@10110.68,7594.78 C78.2@10113.34,7594.78 ; C81.2@10112.68,7921.78 10113,7922.1 v1(10113,7966) 10113.46,7965.54 v1(10498.96,7965.54) ; C78.2@10113.68,7594.44 C78.2@10113.34,7594.78 ; U12.14@10119.04,7872.7 10082.24,7872.7 10066.64,7857.1 10066.64,7673.33 10110.19,7629.78 10110.19,7597.94 C78.2@10113.34,7594.78 ; C80.2@10497.32,7594.18 10497.64,7594.5 v1(10497.64,7637.56) ; C77.2@10499.55,7922.18 C77.2@10498.32,7922.18 10498.96,7922.82 v1(10498.96,7965.54) ; v1(10894.89,7661.66) 10894.89,7600.13 C79.2@10898.85,7596.18 ; C82.2@10895.89,7914.3 10895.89,7880.41 U8.14@10903.21,7873.09 ; C82.2@10897.5,7920 10897.5,7963.93 v1@10895.89,7965.54 ; TP36.1@11665,7892.13 11591.59,7965.54 v1@10895.89,7965.54 ; v1(10498.96,7965.54) v1@10895.89,7965.54
  Bottom Layer w25: v2(3566.5,7765.5) 4088.5,7765.5 4089,7765 ; L10.1@4089,7891.5 4089,7765 ; U14.1@5122,7497 5104.69,7497 5061.69,7454 4170.47,7454 4089,7535.47 4089,7765
  Bottom Layer w30: C102.2@11564.73,8220.25 11618.75,8220.25 11750,8089 11750,7977.13 TP36.1@11665,7892.13 11665,7804.69 R143.1@11664.5,7804.19 11665.5,7803.18 C92.1@11665.5,7740.71 11665.4,7740.61 U16.5@11665.4,7681.05
3.3V_1: C37.2 L10.2 U5.4 | length 253.4
  Bottom Layer w15: 4255.5,7943.63 4275.72,7943.63 4292.5,7960.41 U5.4@4292.5,8001.05
  Bottom Layer w20: L10.2@4090,7953 4090.5,7953.5 C37.2@4153,7953.5 ; C37.2@4153,7951 4160.37,7943.63 4255.5,7943.63
3.3V_2: C34.2 L9.2 R107.1 U3.4 | length 566.2
  Bottom Layer w20: R107.1@9213,7773.5 9402.78,7773.5 9431.14,7745.14 ; U3.4@9431.14,7693.99 9431.14,7745.14 ; L9.2@9707,7767.5 C34.2@9641,7767.5 9453.5,7767.5 9431.14,7745.14
3.3V_3: C32.2 L7.2 R138.1 U1.4 | length 434.1
  Bottom Layer w20: C32.2@2387.33,8070.53 2412.75,8045.1 2464.97,8045.1 U1.4@2466.55,8043.53 2508.13,8043.53 2564.51,8099.91 R138.1@2564.51,8255.85 L7.2@2630.96,8255.85
5V: C89.1 C90.1 C91.1 C96.2 C100.2 C104.2 J2.4 J3.4 J4.4 J5.4 J14.4 J34.4 J37.4 J38.4 J39.4 J71.48 J71.84 J71.98 J71.112 L14.2 R144.2 TP35.1 U16.1 U16.3 U19.5 U20.5 U22.5 | length 14761.6
  Top Layer w20: J71.112@9509.1,8238.07 9509.1,8144.28 9522.38,8131 9716.15,8131 9729.58,8144.42 ; J71.98@9729.58,8238.07 9729.58,8144.42 ; J71.84@9950.05,8238.07 9950.05,8131.53 9949.54,8131.02 ; v1(9951.96,8003.58) 9949.54,8006 9949.54,8131.02 ; v1@10642.92,8003.58 10642.96,8003.62 J71.48@10642.96,8238.07 ; v2(11414.52,7229) 11414.52,7250.44 11440,7275.91 11470,7305.91 v2(11750,7305.91) ; 9729.58,8144.42 9742.98,8131.02 9949.54,8131.02
  Top Layer w30: TP35.1@11666,8039 11750,7955 v2(11750,7305.91) v2@11750,7304.91
  Top Layer w40: J2.4@7781.32,75.11 J2.4@7781.32,225.11 J3.4@7781.32,1184.74 J37.4@7781.32,1996.37 J37.4@7781.32,2146.37 J5.4@7781.32,2957 J5.4@7781.32,3107 J14.4@7781.32,3916.63 J14.4@7781.32,4066.63 J39.4@7781.32,4878.26 J39.4@7781.32,5028.26 J4.4@7781.32,5838.89 J4.4@7781.32,5988.89 J34.4@7781.32,6798.52 J34.4@7781.32,6948.52 J38.4@7781.32,7760.15
  Pwr Layer w30: J38.4@7781.32,7910.15 7781.32,7953.03 7831.87,8003.58 v1(9951.96,8003.58)
  Bottom Layer w20: U19.5@7738.39,1330.72 7737.59,1329.92 C96.2@7737.59,1281.34 7737.5,1281.24 7737.5,1228.56 J3.4@7781.32,1184.74 ; U20.5@7738.39,4212.61 7737.59,4211.81 7737.59,4163.23 C100.2@7737.5,4163.13 7737.5,4110.45 J14.4@7781.32,4066.63 ; U22.5@7738.39,7094.5 7737.59,7093.7 7737.59,7045.12 C104.2@7737.5,7045.02 7737.5,6992.34 J34.4@7781.32,6948.52 ; R144.2@11414.52,7181.1 v2(11414.52,7229) ; U16.3@11590.6,7572.78 11590.6,7608.51 11606,7623.91 11649,7623.91 11665.4,7607.51 U16.1@11665.4,7572.78
  Bottom Layer w30: v1(9951.96,8003.58) 9952,8003.54 v1(10642.96,8003.54) 11630.54,8003.54 TP35.1@11666,8039
  Bottom Layer w40: J38.4@7781.32,7760.15 J38.4@7781.32,7910.15
12V_INT: J75.1 J78.3 J78.4 | length 816.8
  Top Layer w50: J78.3@11700,4930 J78.4@11700,5030 J75.1@11700,5746.8
+12V: C12.1 C86.1 C87.1 C88.1 C105.1 D1.1 D2.1 D3.1 D4.1 D5.1 D6.1 J75.2 J79.1 J80.1 J81.1 K1.1 K2.1 K3.1 K4.1 K5.1 K6.1 TP14.1 U15.3 U15.5 | length 37355.6
  Top Layer w25: v1(9036.76,8357.47) 9036.76,7895.24 v2(9037,7895)
  Top Layer w40: J79.1@8235,77 J80.1@8235,2958 J81.1@8235,5837 8235,6861 8774,7400 9879,7400 ; TP14.1@9879,7561.36 9879,7400 ; C86.1@11609.79,6871.91 11528.09,6871.91 11178,7222 10381.41,7222 10203.41,7400 9879,7400
  Top Layer w50: C86.1@11609.79,6871.91 11609.79,6815.79 11490,6696 11490,5965.02 11576.02,5879 J75.2@11700,5879
  Gnd Layer w20: K1.1@1100.44,112.62 890,323.06 890,803 K2.1@1106,1019 890,1235 890,1839 1094,2043 1094,2663.43 K3.1@1106.13,2675.56
  Pwr Layer w20: K6.1@1102,6402 891,6191 891,5703.06 K5.1@1104.44,5489.62 890,5275.18 890,3799 K4.1@1102,3587 890,3375 890,2891.69 K3.1@1106.13,2675.56 1357.69,2424 1806.7,2424 1956.7,2574 1956.7,7264.47
  Pwr Layer w25: 1956.7,7264.47 3146.23,8454 8967,8454 9036.76,8384.24 v1(9036.76,8357.47) ; v2(9037,7895) 9779.57,7895 9879,7795.57 TP14.1@9879,7566.56
  Bottom Layer w20: U15.5@11472.87,7155.91 11502,7155.91 11539.4,7118.51 U15.3@11581.13,7118.51
  Bottom Layer w25: D1.1@643.47,88 1075.82,88 K1.1@1100.44,112.62 ; D2.1@643.47,1001 1088,1001 K2.1@1106,1019 ; D4.1@643.47,3563 1078,3563 K4.1@1102,3587 ; D6.1@643.47,6379 1079,6379 K6.1@1102,6402 ; C105.1@643.93,5652 643.93,5468.46 D5.1@643.47,5468 1082.82,5468 K5.1@1104.44,5489.62
  Bottom Layer w50: C12.1@643.93,2838 643.93,2655.46 D3.1@643.47,2655 1085.57,2655 K3.1@1106.13,2675.56
BV+_N: C16.2 R35.1 R44.2 U3.2 | length 218.1
  Bottom Layer w20: U3.2@9531.14,7693.99 9531.14,7638.42 R35.1@9542.09,7627.47 9542.09,7565.15 C16.2@9542.62,7564.63 9542.62,7488.61 R44.2@9537,7482.99
BV+_P: R56.2 R59.2 U3.3 | length 420
  Bottom Layer w20: U3.3@9481.14,7693.99 9481.14,7641.27 R59.2@9467,7627.12 9467.67,7627.12 9503.57,7591.22 9503.57,7590.12 9504,7589.7 9504,7530.66 9481,7507.66 9481,7463.67 9497.27,7447.4 9629.88,7447.4 R56.2@9632.01,7449.53
BV-_N: C22.2 R62.1 R71.2 U3.6 | length 240.5
  Bottom Layer w20: R71.2@9284,7482.99 9300.99,7482.99 9325.66,7507.66 R62.1@9325.66,7564.63 C22.2@9325.64,7627.47 9331.14,7632.97 U3.6@9331.14,7693.99
BV-_P: R83.2 R86.2 U3.5 | length 268
  Bottom Layer w20: U3.5@9381.14,7693.99 9381.14,7651.15 R86.2@9405.17,7627.12 9404.5,7627.12 9368.59,7591.22 9368.59,7504.41 9390.01,7482.99 R83.2@9412.62,7482.99
CY+_A: J71.49 TP29.1 U8.10 U8.13 U9.9 U9.10 | length 1604
  Top Layer w15: v1(10962.35,7442.18) v1(10962.35,7771.18) v1(10962.35,7929.54)
  Top Layer w20: J71.49@10611.47,8371.93 10611.47,8342.34 10629.37,8324.43 v1(10648,8324.43)
  Pwr Layer w20: v1(10648,8324.43) 10741.57,8324.43 10850,8216 10850,8097.42 10962.39,7985.03 10962.39,7929.58 v1(10962.35,7929.54)
  Bottom Layer w12: U9.9@10903.21,7415.92 U9.10@10903.21,7441.51 10954.68,7441.51 10955.35,7442.18 v1(10962.35,7442.18) ; U8.10@10903.21,7769.59 10960.76,7769.59 v1(10962.35,7771.18)
  Bottom Layer w15: U8.13@10903.21,7846.36 10945.78,7846.36 10962.35,7862.93 v1(10962.35,7929.54)
  Bottom Layer w20: v1(10962.35,7442.18) 10990.19,7414.33 TP29.1@10990.19,7268
CY+_B: J71.53 TP30.1 U10.10 U10.13 U11.9 U11.10 | length 1382.4
  Top Layer w15: J71.53@10548.47,8371.93 10548.47,8333.47 10487.47,8272.47 10487.47,8022.3 10563.32,7946.44 v1(10563.32,7857.18) v1(10563.32,7771.18) 10563.32,7461.33 v1(10563.79,7460.86)
  Bottom Layer w12: U11.9@10504.18,7415.92 U11.10@10504.18,7441.51 10544.44,7441.51 v1(10563.79,7460.86) ; U10.10@10504.18,7769.59 10561.73,7769.59 v1(10563.32,7771.18) ; U10.13@10504.18,7846.36 10552.5,7846.36 v1(10563.32,7857.18)
  Bottom Layer w20: v1(10563.79,7460.86) 10653,7371.65 TP30.1@10653,7300
CY+_C: J71.50 TP31.1 U12.10 U12.13 U13.9 U13.10 | length 1512.5
  Top Layer w15: v1(10610.47,8140) 10611.47,8141 J71.50@10611.47,8238.07
  Pwr Layer w12: v1(10178.19,7450.12) v1(10178.19,7770.78) v1(10178.19,7856.78)
  Pwr Layer w15: v1(10178.19,7856.78) 10189,7845.97 10442.69,7845.97 10610.47,8013.74 v1(10610.47,8140)
  Bottom Layer w12: U13.9@10119.04,7415.52 U13.10@10119.04,7441.12 10169.19,7441.12 v1(10178.19,7450.12) ; U12.10@10119.04,7769.19 10176.59,7769.19 v1(10178.19,7770.78) ; U12.13@10119.04,7845.97 10167.37,7845.97 v1(10178.19,7856.78)
  Bottom Layer w20: TP31.1@10472,8153.63 10489.37,8171 10587,8171 10610.47,8147.53 v1(10610.47,8140)
CY-_A: J71.51 U8.1 U8.4 U9.12 U9.13 | length 1484.1
  Top Layer w15: v1(11074.35,7878.18) v1(11074.35,7796.18) 11074.35,7545.71 v1@11074.65,7545.41
  Top Layer w20: J71.51@10579.97,8371.93 10579.97,8329.03 v1(10589,8320)
  Pwr Layer w20: v1(10589,8320) 10620,8289 10681,8289 10766,8204 10766,8044.42 10932.24,7878.18 v1(11074.35,7878.18)
  Bottom Layer w12: U9.12@10903.21,7492.69 U9.13@10903.21,7518.28 10947.45,7518.28 10974.35,7545.18 v1(11074.88,7545.18) ; v1(11074.35,7796.18) 11134.49,7796.18 U8.4@11135.49,7795.18
  Bottom Layer w15: v1(11074.35,7878.18) 11080.53,7872 11135.44,7872 U8.1@11135.49,7871.95
CY-_B: J71.55 U10.1 U10.4 U11.12 U11.13 | length 1235.1
  Top Layer w15: v1(10675.32,7562.71) v1(10675.32,7796.18) v1@10675.32,7877.18
  Top Layer w20: v1(10491.82,8321.69) 10516.98,8346.85 J71.55@10516.98,8371.93
  Pwr Layer w20: v1(10491.82,8321.69) 10655,8158.51 10655,8082 10675.32,8061.68 v1(10675.32,7878.18)
  Bottom Layer w12: U11.12@10504.18,7492.69 U11.13@10504.18,7518.28 10548.42,7518.28 10592.85,7562.71 v1(10675.32,7562.71) ; v1(10675.32,7796.18) 10735.46,7796.18 U10.4@10736.46,7795.18 ; v1(10675.32,7878.18) 10681.55,7871.95 U10.1@10736.46,7871.95
CY-_C: J71.52 U12.1 U12.4 U13.12 U13.13 | length 1169.6
  Top Layer w15: v1(10290.19,7795.78) v1(10290.19,7877.78) ; v1@10574.98,8130 v1(10576,8131.02) 10579.97,8134.99 J71.52@10579.97,8238.07
  Pwr Layer w12: v1(10290.19,7795.78) 10290.72,7795.25 v1(10290.72,7544.78)
  Pwr Layer w15: v1(10290.19,7877.78) 10543.42,8131.02 v1(10576,8131.02)
  Bottom Layer w12: U13.12@10119.04,7492.3 U13.13@10119.04,7517.89 10144.29,7517.89 10147.15,7520.75 10160.48,7534.06 ; 10160.48,7534.08 10171.19,7544.78 v1(10290.72,7544.78) v1@10292.02,7543.48 ; v1(10290.19,7795.78) 10350.33,7795.78 U12.4@10351.33,7794.78 ; v1(10290.19,7877.78) 10296.41,7871.56 U12.1@10351.33,7871.56
DC+: C1.1 C2.1 C3.1 C4.1 J1.1 J15.1 J17.1 J18.1 J19.1 J21.1 J22.1 J76.1 J76.2 R1.2 R54.1 TP1.1 | length 2974.9
  Top Layer w40: J1.1@11677,400.55 11718,441.55 TP1.1@11718,576
  Top Layer w50: C3.1@10648.51,4131 11699,4131 J76.2@11700,4130 J76.1@11700,4030
  Pwr Layer w30: v1(10064.02,7042.01) 10648.51,6457.51 C4.1@10648.51,5919
  Bottom Layer w30: R54.1@10002.86,7042.01 v1(10064.02,7042.01) ; R1.2@11566,546.14 11566,489.79 11655.24,400.55 J1.1@11677,400.55
DC-: C5.2 C6.2 C7.2 C8.2 J44.1 J45.1 J47.1 J48.1 J49.1 J51.1 J66.1 J77.1 J77.2 R11.1 R69.1 TP9.1 | length 1243.6
  Top Layer w40: J66.1@11677,2745.45 11732,2690.45 TP9.1@11732,2556
  Top Layer w50: J66.1@11677,2976.55 11700,2999.55 J77.2@11700,3630
  Bottom Layer w30: R69.1@9360,6892.01 9378.99,6892.01 9458,6813 C8.2@9464.26,6813 ; R11.1@11570,2558.32 11570,2638.45 J66.1@11677,2745.45
DEBUG: J71.62 TP38.1 | length 624.5
  Top Layer w20: TP38.1@9957,7844.85 10111.7,7844.85 10296.51,8029.65 J71.62@10296.51,8238.07
FAN_CTRL: J71.74 R149.1 R153.1 R158.1 | length 9802.8
  Top Layer w15: v1(10089.36,8125) 10107.53,8143.17 J71.74@10107.53,8238.07
  Top Layer w20: v2(8154,112) 8154,2989.68 v2(8154.32,2990) v2(8154.32,5874) 8154.32,6876.32 8954,7676 v1(9938,7676)
  Pwr Layer w20: v1(9938,7676) 10046,7784 10046,8081.64 v1(10089.36,8125)
  Bottom Layer w20: v2(8154,112) 8197.73,155.73 R149.1@8234.01,155.73 ; v2(8154.32,2990) 8202.32,3038 R153.1@8232,3038 ; v2(8154.32,5874) 8198.32,5918 R158.1@8231.5,5918
FAULT_A: C95.1 J71.69 R147.2 R150.2 | length 10159.7
  Top Layer w20: J71.69@10170.52,8371.93 10170.52,8329.48 v1(10171,8329)
  Pwr Layer w20: v1(10171,8329) 10171,7958.65 10078,7865.65 10078,7432.69 10230.2,7280.49 10476.46,7280.49 10658.19,7098.75 10658.19,6867.81 10875.02,6650.98 v1(11313.02,6650.98)
  Bottom Layer w20: C95.1@7735.5,1438.26 R150.2@7735.5,1503.26 7801.24,1503.26 R147.2@7802,1502.5 9039.38,2739.88 10126.88,2739.88 11138.5,3751.5 11138.5,4431.5 11453,4746 11453,6511 v1(11313.02,6650.98)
